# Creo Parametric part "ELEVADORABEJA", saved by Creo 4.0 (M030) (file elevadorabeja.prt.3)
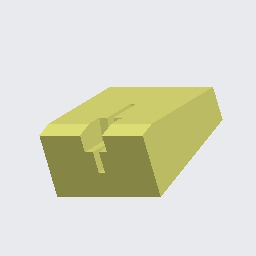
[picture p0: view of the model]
Units: millimeter Newton Second (mmNs); MM, TONNE, SECS

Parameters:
  MODELED_BY = "aj"

Created from: MMNS_PART_SOLID.PRT

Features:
  1. datum plane "RIGHT"
  2. datum plane "TOP"
  3. datum plane "FRONT"
  4. coordinate system
  5. extrusion "Extrude 1"
  6. extruded cut "Extrude 2"
  7. extruded cut "Extrude 3"
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
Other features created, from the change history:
  extruded cut "Extrude 4" (2 times)

Surfaces: 15 plane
